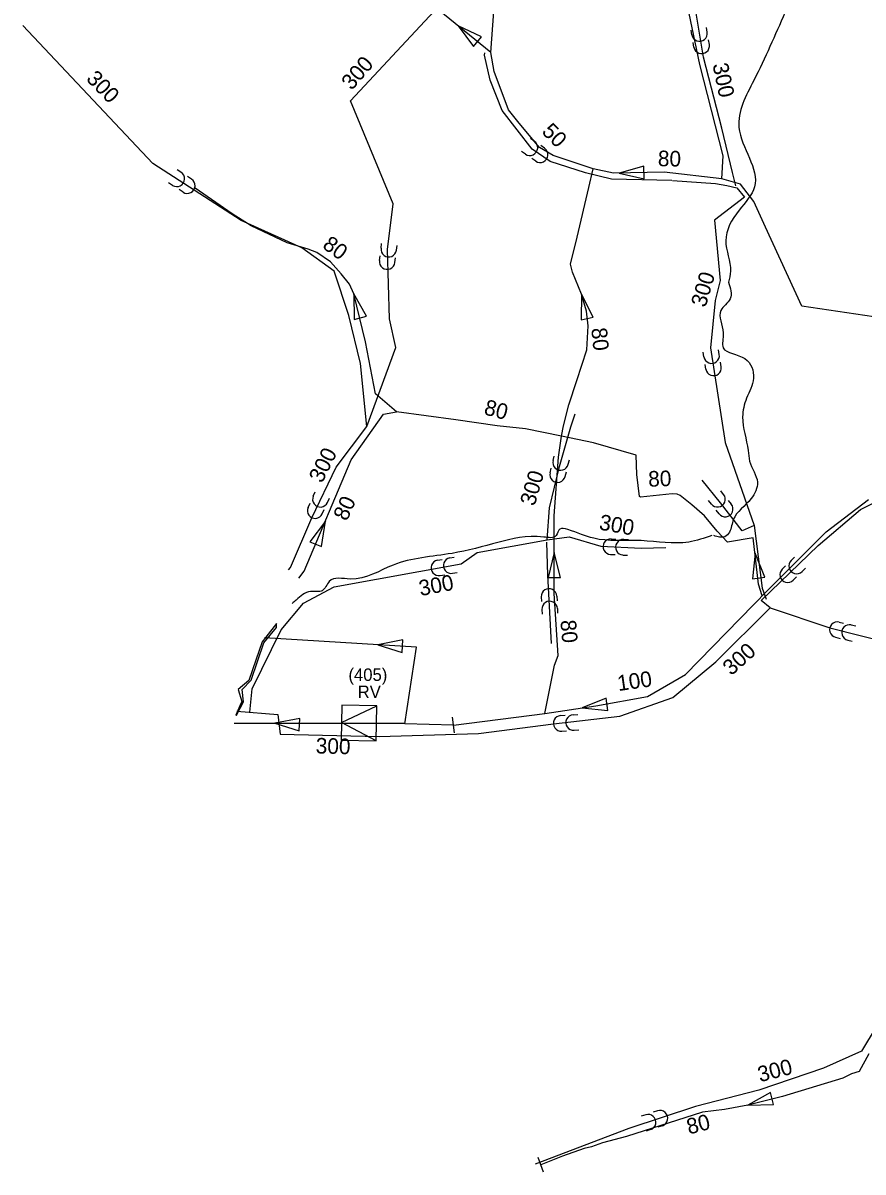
# Model space of a CAD drawing. Extents: x -438814 to -433781, y -1130090 to -1121339.
# Drawn here: x -438788 to -438249, y -1124679 to -1123942 of the extents above; entities that cross this region are included whole.
import ezdxf

# ---------------------------------------------------------------- set-up
doc = ezdxf.new("R2010")
doc.units = 0
for name, color, linetype in [('STAV', 7, 'Continuous'), ('Vrstva 11', 7, 'Continuous'), ('Vrstva 12', 7, 'Continuous'), ('Vrstva 13', 7, 'Continuous'), ('Vrstva 14', 7, 'Continuous'), ('Vrstva 19', 7, 'Continuous'), ('Vrstva 34', 7, 'Continuous'), ('Vrstva 36', 7, 'Continuous'), ('Vrstva 38', 7, 'Continuous'), ('Vrstva 39', 7, 'Continuous'), ('Vrstva 48', 7, 'Continuous'), ('Vrstva 49', 7, 'Continuous'), ('Vrstva 70', 7, 'Continuous')]:
    doc.layers.add(name, color=color, linetype=linetype)

# ---------------------------------------------------------------- blocks, each defined once
blk = doc.blocks.new('REDUK2')
at = {"layer": 'Vrstva 11'}
for p, q in [((11.906, 10.975), (-10.548, 10.975)), ((-10.548, 10.975), (-10.548, -11.657)), ((-10.548, 10.975), (11.906, -0.341)), ((11.906, -11.657), (11.906, 10.975)), ((11.906, -0.341), (-10.548, -11.657)), ((-10.548, -11.657), (11.906, -11.657))]:
    blk.add_line(p, q, dxfattribs=at)

msp = doc.modelspace()

# ---------------------------------------------------------------- linework, layer by layer
at = {"layer": 'Vrstva 11'}
for points in [[(-438442.88, -1124207.02), (-438441.6, -1124200.42), (-438438.29, -1124186.93), (-438433.03, -1124171.38), (-438426.62, -1124151.63), (-438425.76, -1124136.25), (-438426.82, -1124126.85), (-438430.11, -1124115.96), (-438435.77, -1124101.69), (-438437.1, -1124096.6), (-438432.95, -1124079.29), (-438425.3, -1124047.44), (-438422.48, -1124035.55)], [(-438314.06, -1124309.51), (-438316.51, -1124302.05), (-438319.82, -1124272.26), (-438336.48, -1124274.95), (-438342.98, -1124267.91), (-438351.11, -1124258.21), (-438359.34, -1124250.97), (-438366.81, -1124245.05), (-438368.77, -1124244.22), (-438371.81, -1124243.9), (-438392.24, -1124246.22), (-438392.92, -1124245.73), (-438394.67, -1124231.5), (-438394.89, -1124219.29), (-438422.3, -1124211.37), (-438442.88, -1124207.02), (-438466, -1124202.27), (-438484.14, -1124200.36), (-438510.72, -1124196.48), (-438548.74, -1124191.47), (-438562.22, -1124179.81), (-438568.66, -1124146.38), (-438576.25, -1124115.64), (-438578.87, -1124109.52), (-438584.21, -1124102.8), (-438591.16, -1124095.15), (-438599.97, -1124089.17), (-438605.49, -1124087.04), (-438618.88, -1124082.96), (-438641.95, -1124072.08), (-438654.16, -1124064.24), (-438677.87, -1124047.92)], [(-438512.15, -1124392.34), (-438453.67, -1124384.87), (-438420.93, -1124380.11), (-438387.77, -1124374.02), (-438363.32, -1124359.98), (-438310.95, -1124306.32), (-438304.05, -1124299.37), (-438273.08, -1124268.41), (-438245.92, -1124247.58)], [(-438245.72, -1124603.41), (-438251.96, -1124614.54), (-438256.93, -1124616.08), (-438262.32, -1124618.96), (-438301.2, -1124630.58), (-438323.29, -1124636.23), (-438338.38, -1124638.97), (-438352.36, -1124640.67), (-438401.26, -1124656.44), (-438416.53, -1124660.43), (-438423.56, -1124663.01), (-438428.3, -1124664.11), (-438442.18, -1124668.96), (-438456.25, -1124674.44)]]:
    msp.add_lwpolyline(points, dxfattribs=at)
at = {"layer": 'Vrstva 12'}
for p, q in [((-438511.49, -1124397.3), (-438512.81, -1124387.39)), ((-438454.54, -1124679.13), (-438457.96, -1124669.74))]:
    msp.add_line(p, q, dxfattribs=at)
for points in [[(-438575.84, -1124132.13), (-438568.13, -1124130), (-438576.25, -1124115.64)], [(-438430.27, -1124132.45), (-438422.49, -1124130.59), (-438430.11, -1124115.96)], [(-438320.26, -1124298.58), (-438312.34, -1124297.4), (-438318.65, -1124282.16)], [(-438413.15, -1124383.11), (-438414.21, -1124375.18), (-438429.54, -1124381.27)], [(-438306.8, -1124635.89), (-438308.9, -1124628.18), (-438323.29, -1124636.23)]]:
    msp.add_lwpolyline(points, close=True, dxfattribs=at)
at = {"layer": 'Vrstva 13'}
for p, q in [((-438488.31, -1123960.72), (-438538.54, -1123919.74)), ((-438543.49, -1124391.29), (-438653.03, -1124391.29))]:
    msp.add_line(p, q, dxfattribs=at)
for points in [[(-438339.96, -1124041.86), (-438339.19, -1124027.17), (-438354.13, -1123968.53), (-438362.05, -1123930.71), (-438383.31, -1123905.62), (-438391.01, -1123883.43), (-438409.98, -1123853.88), (-438454.8, -1123791.15), (-438466.52, -1123791.91)], [(-438087.24, -1124107.32), (-438135.67, -1124122.18), (-438154.23, -1124128.52), (-438172.8, -1124139.61), (-438230.97, -1124132.14), (-438288.66, -1124123.51), (-438311.91, -1124072.81), (-438319.59, -1124056.35), (-438327.96, -1124045.25), (-438339.96, -1124041.86), (-438377.03, -1124037.56), (-438409.62, -1124038.24), (-438422.48, -1124035.55), (-438448.29, -1124026.95), (-438457.11, -1124021.74), (-438470.02, -1124006.12), (-438477.01, -1123997.55), (-438486.06, -1123973.09), (-438488.31, -1123960.72), (-438482.88, -1123887.58), (-438483.1, -1123883.34)], [(-438611.36, -1124298.04), (-438607.93, -1124293.61), (-438577.83, -1124222.09), (-438557.1, -1124192.91), (-438548.74, -1124191.47)], [(-438453.67, -1124384.87), (-438447.34, -1124353.84), (-438445.07, -1124347.73), (-438447.56, -1124307.87), (-438447.56, -1124262.81), (-438447.56, -1124258.11), (-438444.9, -1124220.51), (-438442.88, -1124207.02)], [(-438512.15, -1124392.34), (-438543.49, -1124391.63), (-438536.02, -1124342.27), (-438633.41, -1124336.42)]]:
    msp.add_lwpolyline(points, dxfattribs=at)
at = {"layer": 'Vrstva 14'}
for points in [[(-438499.36, -1123956.87), (-438494.3, -1123950.67), (-438509.23, -1123943.65)], [(-438389.82, -1124041.83), (-438389.99, -1124033.83), (-438405.9, -1124038.16)], [(-438604.31, -1124274.69), (-438596.94, -1124277.79), (-438594.42, -1124261.49)], [(-438451.56, -1124297.66), (-438443.56, -1124297.66), (-438447.56, -1124281.66)], [(-438545.12, -1124345.73), (-438544.64, -1124337.74), (-438560.85, -1124340.78)], [(-438611.2, -1124396.16), (-438610.72, -1124388.18), (-438626.93, -1124391.21)]]:
    msp.add_lwpolyline(points, close=True, dxfattribs=at)
at = {"layer": 'Vrstva 19'}
msp.add_line((-438640.64, -1124071.78), (-438640.64, -1124071.78), dxfattribs=at)
at = {"layer": 'Vrstva 34'}
for points in [[(-438618.18, -1124292.86), (-438616.82, -1124291.28), (-438603.03, -1124259.33), (-438587.5, -1124226.84), (-438567.82, -1124200.86), (-438571.9, -1124160.37), (-438579.29, -1124129.63), (-438588.73, -1124101.17), (-438609.56, -1124086.22), (-438648.41, -1124068.62), (-438705.23, -1124031.94), (-438788.44, -1123943.51)], [(-438308.92, -1124317.08), (-438270.78, -1124330.05), (-438232.63, -1124339.64), (-438193.93, -1124319.41), (-438110.46, -1124306.7), (-438076.83, -1124294.13), (-438044.07, -1124289.63), (-437999.41, -1124284.16), (-437947.43, -1124273.24), (-437905, -1124250.33), (-437868.85, -1124217.12), (-437841.76, -1124189.51), (-437857.04, -1124146.16), (-437823.32, -1124112.77), (-437798.27, -1124098.47), (-437778.05, -1124070.78), (-437758.37, -1124050.48), (-437737.69, -1124057.16), (-437694.33, -1124068.4)], [(-438651.16, -1124383.4), (-438624.86, -1124385.67), (-438623.42, -1124398.12), (-438559.85, -1124399.77), (-438496.06, -1124397.82), (-438448.11, -1124391.65), (-438405.45, -1124386.56), (-438371.48, -1124374.64), (-438343.9, -1124351.74), (-438308.92, -1124317.08), (-438314.79, -1124312.41), (-438278.32, -1124277.04), (-438250.99, -1124254.05), (-438206.56, -1124231.61)]]:
    msp.add_lwpolyline(points, dxfattribs=at)
at = {"layer": 'Vrstva 36'}
for points in [[(-438331.07, -1124046.44), (-438333.12, -1124037.74), (-438339.96, -1124009.42), (-438351.73, -1123963.91), (-438357.38, -1123930.49), (-438380.02, -1123902.18), (-438387.48, -1123880.05), (-438405.81, -1123851.29), (-438437.69, -1123807.22), (-438456.25, -1123781.63), (-438506.44, -1123713.82), (-438523.22, -1123647.28), (-438584.56, -1123598.88)], [(-438567.82, -1124200.86), (-438549.24, -1124150.11), (-438553.35, -1124131.76), (-438554.62, -1124087.16), (-438550.82, -1124057.86), (-438578.33, -1123991.75), (-438524.57, -1123934.38), (-438630.16, -1123854.33)], [(-438372.19, -1124043.02), (-438410.87, -1124042.12), (-438427.57, -1124038.05), (-438450.2, -1124030.81), (-438461.74, -1124022.88), (-438480.96, -1123998.07), (-438488.66, -1123978.6), (-438492.28, -1123962.52), (-438492.16, -1123961.14)], [(-438371.71, -1124043.03), (-438344.03, -1124044.86), (-438336.76, -1124046.12), (-438330.43, -1124047.71), (-438325.53, -1124053.6), (-438344.66, -1124068.31), (-438341.04, -1124107.22), (-438344.21, -1124119.87), (-438347.37, -1124150.24), (-438337.88, -1124210.97), (-438319.33, -1124264.41), (-438314.08, -1124304.57), (-438311.64, -1124311.6)], [(-438452.19, -1124273.53), (-438450.66, -1124252.99), (-438444.09, -1124226.49), (-438436.85, -1124200.91), (-438434.16, -1124192.76)], [(-438319.33, -1124264.41), (-438326.93, -1124267.68), (-438340.97, -1124249.8), (-438352.74, -1124235.13)], [(-438642.93, -1124384.11), (-438641.36, -1124369.01), (-438622.81, -1124331.25), (-438608.55, -1124314.04), (-438588.86, -1124303.62), (-438507.38, -1124288.9), (-438496.96, -1124281.66), (-438452.19, -1124273.53), (-438437.93, -1124271.49), (-438417.56, -1124277.6), (-438391.84, -1124278.75), (-438376, -1124278.38)], [(-438449.37, -1124340.04), (-438451.64, -1124296.11), (-438452.35, -1124274.97)], [(-438072.31, -1124326.82), (-438070.72, -1124338.14), (-438084.53, -1124374.6), (-438114.66, -1124405.79), (-438142.73, -1124423), (-438145.44, -1124435.91), (-438147.89, -1124449.85), (-438144.26, -1124487.89), (-438198.59, -1124497.85), (-438204.18, -1124509.07), (-438223.42, -1124565.68), (-438241.08, -1124586.06), (-438250.36, -1124601.69), (-438274.72, -1124612.47), (-438316.37, -1124626.51), (-438356.89, -1124637.15), (-438399.67, -1124651.19), (-438459.74, -1124674)]]:
    msp.add_lwpolyline(points, dxfattribs=at)
at = {"layer": 'Vrstva 38'}
for p, q in [((-438687.06, -1124037.71), (-438689.58, -1124036.09)), ((-438680.34, -1124042.05), (-438682.86, -1124040.43)), ((-438692.48, -1124046.11), (-438695, -1124044.49)), ((-438685.76, -1124050.45), (-438688.28, -1124048.83)), ((-438602.17, -1124245.43), (-438600.92, -1124242.7)), ((-438593.08, -1124249.58), (-438591.83, -1124246.86)), ((-438605.5, -1124252.7), (-438604.25, -1124249.97)), ((-438596.4, -1124256.86), (-438595.16, -1124254.13)), ((-438295.54, -1124286.7), (-438293.4, -1124284.6)), ((-438301.25, -1124292.3), (-438299.11, -1124290.2)), ((-438288.54, -1124293.84), (-438286.4, -1124291.74)), ((-438294.25, -1124299.44), (-438292.11, -1124297.34)), ((-438264.78, -1124326.3), (-438261.86, -1124326.97)), ((-438256.99, -1124328.09), (-438254.06, -1124328.76)), ((-438267.02, -1124336.04), (-438264.1, -1124336.72)), ((-438259.23, -1124337.83), (-438256.3, -1124338.51)), ((-438443.49, -1124386.3), (-438440.5, -1124386.07)), ((-438435.51, -1124385.7), (-438432.52, -1124385.48)), ((-438442.75, -1124396.27), (-438439.76, -1124396.05)), ((-438434.77, -1124395.68), (-438431.78, -1124395.46))]:
    msp.add_line(p, q, dxfattribs=at)
for centre, start, end in [((-438689.77, -1124041.91), 237.15049, 57.15156), ((-438683.05, -1124046.25), 237.15049, 57.15156), ((-438597.62, -1124247.5), 155.42113, 335.4222), ((-438600.95, -1124254.78), 155.42113, 335.4222), ((-438292.04, -1124290.27), 134.45249, 314.45356), ((-438297.75, -1124295.87), 134.45249, 314.45356), ((-438265.9, -1124331.17), 77.05789, 257.05896), ((-438258.11, -1124332.96), 77.05789, 257.05896), ((-438443.12, -1124391.28), 94.24012, 274.24119), ((-438435.14, -1124390.69), 94.24012, 274.24119)]:
    msp.add_arc(centre, 5, start, end, dxfattribs=at)
at = {"layer": 'Vrstva 39'}
for p, q in [((-438359.24, -1123949.51), (-438359.74, -1123946.55)), ((-438349.38, -1123947.84), (-438349.88, -1123944.88)), ((-438357.9, -1123957.4), (-438358.41, -1123954.44)), ((-438348.04, -1123955.73), (-438348.54, -1123952.77)), ((-438460.35, -1124017.77), (-438462.83, -1124016.07)), ((-438453.76, -1124022.3), (-438456.23, -1124020.6)), ((-438466.01, -1124026.02), (-438468.49, -1124024.32)), ((-438459.42, -1124030.54), (-438461.89, -1124028.85)), ((-438558.71, -1124086.37), (-438558.33, -1124083.39)), ((-438548.8, -1124087.65), (-438548.41, -1124084.68)), ((-438559.74, -1124094.3), (-438559.35, -1124091.33)), ((-438549.82, -1124095.58), (-438549.44, -1124092.61)), ((-438351.52, -1124156.06), (-438351.98, -1124153.09)), ((-438341.64, -1124154.52), (-438342.1, -1124151.55)), ((-438350.29, -1124163.96), (-438350.75, -1124161)), ((-438340.41, -1124162.42), (-438340.87, -1124159.46)), ((-438448.29, -1124222.65), (-438447.57, -1124219.74)), ((-438450.22, -1124230.42), (-438449.5, -1124227.5)), ((-438438.59, -1124225.05), (-438437.86, -1124222.14)), ((-438440.51, -1124232.82), (-438439.79, -1124229.91)), ((-438338.88, -1124244.37), (-438340.73, -1124242.01)), ((-438346.74, -1124250.55), (-438348.59, -1124248.19)), ((-438333.93, -1124250.66), (-438335.79, -1124248.3)), ((-438341.8, -1124256.84), (-438343.65, -1124254.48)), ((-438411, -1124272.89), (-438408, -1124273.03)), ((-438403.01, -1124273.25), (-438400.01, -1124273.38)), ((-438522.5, -1124286.55), (-438519.55, -1124286.02)), ((-438514.63, -1124285.13), (-438511.68, -1124284.6)), ((-438411.44, -1124282.88), (-438408.44, -1124283.02)), ((-438403.45, -1124283.24), (-438400.45, -1124283.37)), ((-438520.72, -1124296.39), (-438517.77, -1124295.86)), ((-438512.85, -1124294.97), (-438509.9, -1124294.44)), ((-438455.92, -1124310.14), (-438455.77, -1124313.14)), ((-438445.93, -1124309.63), (-438445.78, -1124312.63)), ((-438455.51, -1124318.13), (-438455.35, -1124321.13)), ((-438445.52, -1124317.62), (-438445.37, -1124320.61)), ((-438381.28, -1124639.9), (-438384.13, -1124640.83)), ((-438388.89, -1124642.39), (-438391.73, -1124643.32)), ((-438385.77, -1124651.89), (-438388.62, -1124652.83)), ((-438378.17, -1124649.4), (-438381.02, -1124650.33))]:
    msp.add_line(p, q, dxfattribs=at)
for centre, start, end in [((-438354.31, -1123948.67), 189.5971, 9.59817), ((-438352.97, -1123956.56), 189.5971, 9.59817), ((-438463.18, -1124021.89), 235.53025, 55.53133), ((-438456.59, -1124026.42), 235.53025, 55.53133), ((-438553.75, -1124087.01), 172.62343, 352.6245), ((-438554.78, -1124094.94), 172.62343, 352.6245), ((-438346.58, -1124155.29), 188.87741, 8.87848), ((-438345.35, -1124163.19), 188.87741, 8.87848), ((-438443.44, -1124223.85), 166.08442, 346.08549), ((-438445.36, -1124231.62), 166.08442, 346.08549), ((-438342.81, -1124247.46), 218.14774, 38.14881), ((-438337.87, -1124253.75), 218.14774, 38.14881), ((-438411.22, -1124277.89), 87.4505, 267.45157), ((-438403.23, -1124278.24), 87.4505, 267.45157), ((-438521.61, -1124291.47), 100.2385, 280.23957), ((-438513.74, -1124290.05), 100.2385, 280.23957), ((-438450.93, -1124309.89), 2.94878, 182.94985), ((-438450.52, -1124317.88), 2.94878, 182.94985), ((-438379.72, -1124644.65), 288.16815, 108.16922), ((-438387.33, -1124647.14), 288.16815, 108.16922)]:
    msp.add_arc(centre, 5, start, end, dxfattribs=at)
at = {"layer": 'Vrstva 70'}
for points in [[(-438651.37, -1124385.99), (-438646.94, -1124377.5), (-438647.8, -1124369.55), (-438642.1, -1124363.51), (-438633.82, -1124339.51), (-438625.7, -1124329.67), (-438625.7, -1124327.21)], [(-438625.7, -1124327.21), (-438632.61, -1124335.87), (-438635.01, -1124338.88), (-438639.06, -1124350.64)], [(-438639.06, -1124350.64), (-438643.59, -1124363.78), (-438650.28, -1124369.64), (-438648.05, -1124377.24), (-438649.34, -1124380.12), (-438651.29, -1124384.47), (-438651.97, -1124386.01)], [(-438651.97, -1124386.01), (-438651.37, -1124385.99)]]:
    msp.add_lwpolyline(points, dxfattribs=at)
for points in [[(-438272.48, -1123825.81), (-438280.98, -1123839.11), (-438286.48, -1123854.14), (-438284.48, -1123881.18), (-438286.98, -1123903.22), (-438299.5, -1123935.28), (-438319.53, -1123978.85), (-438329.04, -1124008.91), (-438319, -1124047), (-438329.01, -1124062.04), (-438337.52, -1124081.58), (-438334.52, -1124101.12), (-438335.81, -1124108.24)], [(-438335.81, -1124108.24), (-438334.65, -1124118.84), (-438340.64, -1124126.33), (-438339.14, -1124140.79), (-438339.14, -1124150.27), (-438325.17, -1124157.26), (-438319.69, -1124169.73), (-438324.17, -1124182.71), (-438326.67, -1124194.68), (-438323.18, -1124216.13), (-438322.18, -1124223.12), (-438317.19, -1124236.59), (-438321.18, -1124247.07), (-438332.65, -1124260.54), (-438335.15, -1124268.52), (-438338.14, -1124271.52), (-438345.17, -1124270.75)], [(-438346.36, -1124270.75), (-438361.29, -1124274.93), (-438391.75, -1124274.03), (-438422.22, -1124272.54), (-438438.94, -1124266.86), (-438444.02, -1124266.56), (-438446.28, -1124270.72), (-438454.26, -1124271.71), (-438483.69, -1124275.21), (-438513.12, -1124282.2), (-438551.02, -1124289.69), (-438578.46, -1124298.67), (-438591.92, -1124300.17), (-438596.41, -1124306.16), (-438603.89, -1124306.66), (-438613.17, -1124312.15), (-438615.62, -1124314.33)]]:
    msp.add_spline(points, degree=3, dxfattribs=at)

# ---------------------------------------------------------------- block references
at = {"layer": 'STAV', "rotation": 178.85302660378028}
msp.add_blockref('REDUK2', (-438572.19, -1124391.39), dxfattribs=at)

# ---------------------------------------------------------------- texts
at = {"layer": 'Vrstva 19'}
for s, rotation, p in [('50', 314.97409, (-438456.1, -1124012.11)), ('80', 358.80526, (-438381.16, -1124033.74)), ('80', 323.94902, (-438596.92, -1124085.8)), ('80', 275.81417, (-438423.81, -1124137.83)), ('80', 345.24603, (-438493.21, -1124192.87)), ('80', 1.79005, (-438387.14, -1124239.45)), ('80', 65.77511, (-438580.66, -1124261.96)), ('80', 274.85098, (-438443.62, -1124325.25)), ('100', 8.12569, (-438406.41, -1124370.57)), ('80', 14.53923, (-438361.13, -1124655.09))]:
    msp.add_text(s, height=10, rotation=rotation, dxfattribs=at).set_placement(p)
for s, p in [('(405)', (-438579.62, -1124364.03)), ('  RV', (-438579.62, -1124375.03))]:
    msp.add_text(s, height=8, dxfattribs=at).set_placement(p)
at = {"layer": 'Vrstva 48'}
for rotation, p in [(314.27406, (-438748.42, -1123978.22)), (63.45539, (-438596.59, -1124237.65)), (41.73607, (-438333.96, -1124361.06)), (358.50378, (-438600.71, -1124410.54))]:
    msp.add_text('300', height=10, rotation=rotation, dxfattribs=at).set_placement(p)
at = {"layer": 'Vrstva 49'}
for rotation, p in [(49.09136, (-438577.51, -1123985.52)), (281.84042, (-438346.08, -1123968.57)), (73.69028, (-438350.49, -1124124.79)), (73.69028, (-438460.18, -1124252.24)), (349.75805, (-438419.25, -1124266.83)), (10.80488, (-438533.39, -1124309.62)), (14.53923, (-438315.55, -1124621.57))]:
    msp.add_text('300', height=10, rotation=rotation, dxfattribs=at).set_placement(p)

doc.saveas('drawing.dxf')
